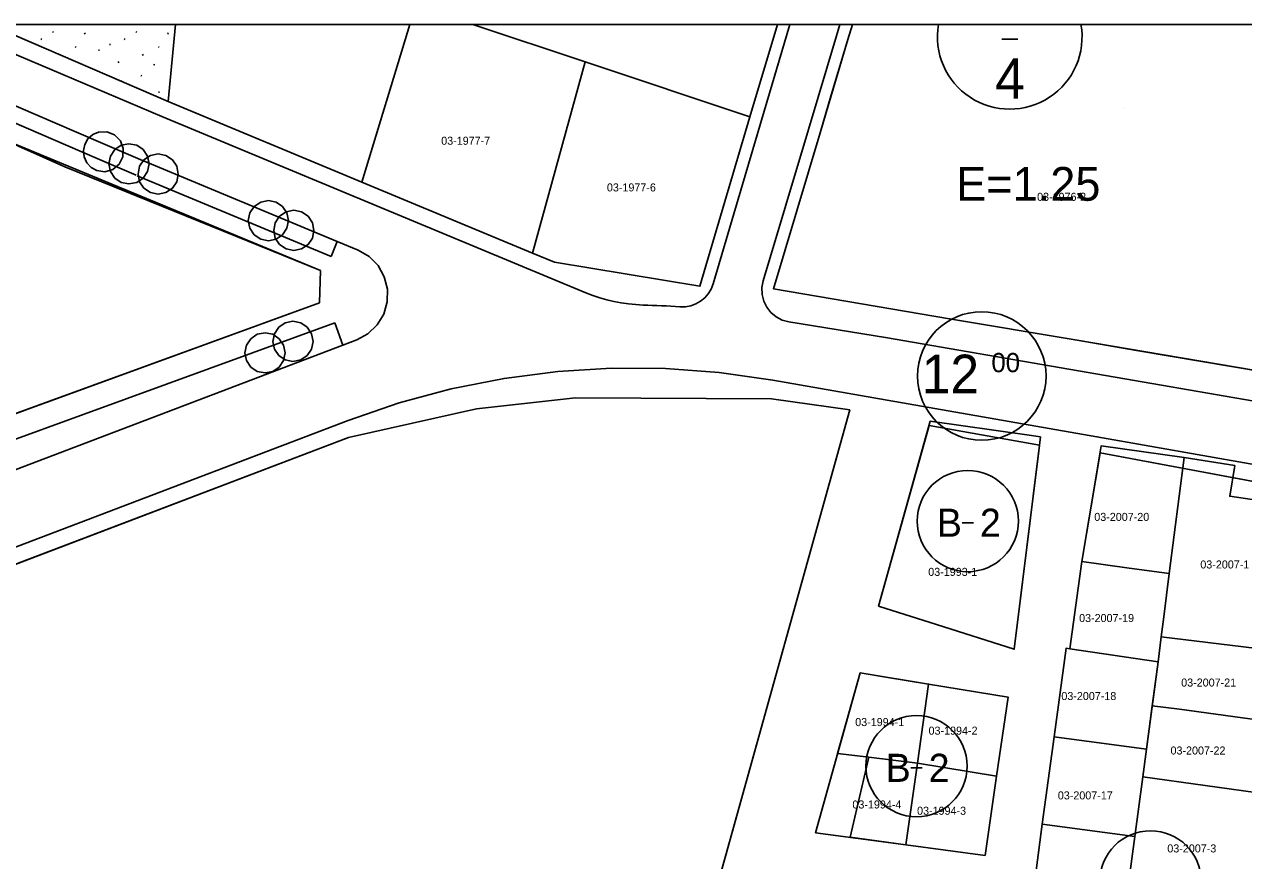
# Model space of a CAD drawing. Extents: x 413946 to 415528, y 4453939 to 4454944.
# Drawn here: x 414198.6 to 414350.4, y 4454839.9 to 4454944 of the extents above; entities that cross this region are included whole.
import ezdxf

# ---------------------------------------------------------------- set-up
doc = ezdxf.new("R2010")
doc.units = 0
for name, color, linetype in [('0_KADASTRO', 7, 'Continuous'), ('0_ÇERÇEVE', 7, 'Continuous'), ('Level 27', 7, 'Continuous'), ('Level 28', 7, 'Continuous'), ('Level 34', 7, 'Continuous'), ('Level 41', 7, 'Continuous'), ('Level 54', 7, 'Continuous'), ('Level 62', 7, 'Continuous'), ('SEMBOL', 7, 'Continuous'), ('SNR_FONKSIYON', 7, 'Continuous')]:
    doc.layers.add(name, color=color, linetype=linetype)

msp = doc.modelspace()

# ---------------------------------------------------------------- linework, layer by layer
at = {"layer": '0_KADASTRO'}
for points in [[(414246.61, 4454943.96), (414240.66, 4454924.31), (414216.52, 4454934.35), (414217.44, 4454943.96)], [(414217.44, 4454943.96), (414246.61, 4454943.96)], [(414254.45, 4454943.96), (414268.47, 4454939.28), (414261.9, 4454915.48), (414240.66, 4454924.31), (414246.61, 4454943.96)], [(414246.61, 4454943.96), (414254.45, 4454943.96)], [(414254.45, 4454943.96), (414292.38, 4454943.96)], [(414292.38, 4454943.96), (414288.97, 4454932.45), (414268.47, 4454939.28), (414254.45, 4454943.96)], [(414364.2, 4454943.96), (414356.8, 4454900.03), (414337.07, 4454903.37), (414329.44, 4454904.67), (414313.82, 4454907.32), (414291.88, 4454911.04), (414297.69, 4454930.45), (414299.05, 4454935), (414301.17, 4454942.09), (414301.73, 4454943.96)], [(414301.73, 4454943.96), (414364.2, 4454943.96)]]:
    msp.add_lwpolyline(points, dxfattribs=at)
for points in [[(414261.9, 4454915.48), (414268.47, 4454939.28), (414288.97, 4454932.45), (414282.73, 4454911.35), (414264.63, 4454914.35)], [(414112.98, 4454904.87), (414193.33, 4454930.76), (414235.49, 4454913.3), (414235.37, 4454909.28), (414125.89, 4454869.42)], [(414096.99, 4454835.77), (414098.7, 4454839.14), (414238.98, 4454892.53), (414254.93, 4454896.1), (414267.24, 4454897.45), (414291.64, 4454897.36), (414301.38, 4454895.97), (414237.57, 4454666.8), (414236.56, 4454663.13), (414213.19, 4454675.19), (414204.39, 4454687.27), (414188.47, 4454709.34), (414167.47, 4454738.38)], [(414304.98, 4454871.51), (414311.4, 4454894.55), (414315.23, 4454894), (414323.43, 4454892.84), (414325.13, 4454892.59), (414324.92, 4454890.87), (414321.86, 4454866.17), (414312.17, 4454869.24)], [(414330.3, 4454877.07), (414331.21, 4454882.53), (414332.7, 4454891.5), (414343, 4454890.03), (414341.16, 4454875.58), (414335.89, 4454876.3)], [(414340.17, 4454867.72), (414340.49, 4454870.19), (414341.16, 4454875.58), (414343, 4454890.03), (414349.31, 4454889.04), (414348.7, 4454885.22), (414358.7, 4454883.73), (414357.14, 4454871.64), (414356.23, 4454865.76)], [(414328.8, 4454866.22), (414330.3, 4454877.07), (414335.89, 4454876.3), (414341.16, 4454875.58), (414340.49, 4454870.19), (414340.17, 4454867.72), (414339.77, 4454864.6)], [(414339.04, 4454859.14), (414339.77, 4454864.6), (414340.17, 4454867.72), (414356.23, 4454865.76), (414354.79, 4454857.02), (414342.43, 4454858.69)], [(414326.83, 4454855.25), (414328.31, 4454866.29), (414328.8, 4454866.22), (414339.77, 4454864.6), (414338.32, 4454853.74)], [(414299.88, 4454853.18), (414302.67, 4454863.22), (414306.12, 4454862.65), (414311.21, 4454861.83), (414309.81, 4454851.98), (414303.77, 4454852.71)], [(414309.81, 4454851.98), (414311.21, 4454861.83), (414321.1, 4454860.2), (414319.67, 4454850.37)], [(414337.87, 4454850.29), (414338.32, 4454853.74), (414339.04, 4454859.14), (414342.43, 4454858.69), (414354.79, 4454857.02), (414353.41, 4454848.13)], [(414325.36, 4454844.37), (414326.83, 4454855.25), (414338.32, 4454853.74), (414337.87, 4454850.29), (414336.89, 4454842.85)], [(414301.42, 4454842.75), (414303.77, 4454852.71), (414309.81, 4454851.98), (414308.36, 4454841.83)], [(414308.36, 4454841.83), (414309.81, 4454851.98), (414319.67, 4454850.37), (414318.23, 4454840.49)], [(414335.69, 4454833.87), (414336.89, 4454842.85), (414337.87, 4454850.29), (414353.41, 4454848.13), (414351.45, 4454831.76)], [(414324.04, 4454834.47), (414325.36, 4454844.37), (414336.89, 4454842.85), (414335.69, 4454833.87), (414335.56, 4454832.91)]]:
    msp.add_lwpolyline(points, close=True, dxfattribs=at)
at = {"layer": '0_ÇERÇEVE'}
msp.add_lwpolyline([(413945.57, 4454943.96), (415494.14, 4454943.96), (415494.14, 4453939.48), (413945.57, 4453939.48)], close=True, dxfattribs=at)
at = {"layer": 'Level 27'}
for p, q in [((414311.26, 4454894.04), (414325.01, 4454891.56)), ((414325.01, 4454891.56), (414321.86, 4454866.17)), ((414330.3, 4454877.07), (414332.55, 4454890.62)), ((414332.55, 4454890.62), (414358.97, 4454885.69)), ((414328.8, 4454866.22), (414330.3, 4454877.07)), ((414312.17, 4454869.24), (414304.98, 4454871.51)), ((414321.86, 4454866.17), (414312.17, 4454869.24)), ((414326.83, 4454855.25), (414328.31, 4454866.29)), ((414328.31, 4454866.29), (414328.8, 4454866.22)), ((414302.67, 4454863.22), (414311.21, 4454861.83)), ((414311.21, 4454861.83), (414321.1, 4454860.2)), ((414321.1, 4454860.2), (414319.67, 4454850.37)), ((414325.36, 4454844.37), (414326.83, 4454855.25)), ((414319.67, 4454850.37), (414318.23, 4454840.49)), ((414324.04, 4454834.47), (414325.36, 4454844.37)), ((414308.36, 4454841.83), (414297.14, 4454843.32)), ((414318.23, 4454840.49), (414308.36, 4454841.83))]:
    msp.add_line(p, q, dxfattribs=at)
at = {"layer": 'Level 28'}
for p, q in [((414292.38, 4454943.96), (414288.97, 4454932.45)), ((414301.17, 4454942.09), (414301.73, 4454943.96)), ((414216.52, 4454934.35), (414195.55, 4454943.39)), ((414297.69, 4454930.45), (414301.17, 4454942.09)), ((414240.66, 4454924.31), (414216.52, 4454934.35)), ((414288.97, 4454932.45), (414282.73, 4454911.35)), ((414193.46, 4454930.78), (414203.67, 4454926.21)), ((414291.88, 4454911.04), (414297.69, 4454930.45)), ((414203.67, 4454926.21), (414235.49, 4454913.3)), ((414261.9, 4454915.48), (414240.66, 4454924.31)), ((414264.63, 4454914.35), (414261.9, 4454915.48)), ((414282.73, 4454911.35), (414264.63, 4454914.35)), ((414235.49, 4454913.3), (414235.37, 4454909.28)), ((414313.82, 4454907.32), (414291.88, 4454911.04)), ((414235.37, 4454909.28), (414024.52, 4454832.51)), ((414329.44, 4454904.67), (414313.82, 4454907.32)), ((414356.8, 4454900.03), (414329.44, 4454904.67)), ((414254.93, 4454896.1), (414267.24, 4454897.45)), ((414267.24, 4454897.45), (414291.64, 4454897.36)), ((414291.64, 4454897.36), (414301.38, 4454895.97)), ((414301.38, 4454895.97), (414237.57, 4454666.8)), ((414238.98, 4454892.53), (414254.93, 4454896.1)), ((414304.98, 4454871.51), (414311.26, 4454894.04)), ((414098.7, 4454839.14), (414238.98, 4454892.53)), ((414297.14, 4454843.32), (414302.67, 4454863.22))]:
    msp.add_line(p, q, dxfattribs=at)
at = {"layer": 'Level 34'}
for points in [[(414364.2, 4454943.96), (414356.8, 4454900.03), (414329.44, 4454904.67), (414313.82, 4454907.32), (414291.88, 4454911.04), (414297.69, 4454930.45), (414301.17, 4454942.09), (414301.73, 4454943.96)], [(414301.73, 4454943.96), (414364.2, 4454943.96)]]:
    msp.add_lwpolyline(points, dxfattribs=at)
at = {"layer": 'Level 41'}
for p, q in [((414202.15, 4454943.01), (414202.28, 4454942.99)), ((414202.15, 4454943.01), (414202.28, 4454942.99)), ((414206.19, 4454942.73), (414206.12, 4454942.89)), ((414206.19, 4454942.73), (414206.12, 4454942.89)), ((414212.52, 4454943.01), (414212.65, 4454942.99)), ((414212.52, 4454943.01), (414212.65, 4454942.99)), ((414216.56, 4454942.73), (414216.49, 4454942.89)), ((414216.56, 4454942.73), (414216.49, 4454942.89)), ((414200.68, 4454942.17), (414200.81, 4454942.07)), ((414200.68, 4454942.17), (414200.81, 4454942.07)), ((414204.95, 4454941.16), (414205.07, 4454941.14)), ((414204.95, 4454941.16), (414205.07, 4454941.14)), ((414209.25, 4454941.47), (414209.38, 4454941.44)), ((414209.25, 4454941.47), (414209.38, 4454941.44)), ((414211.05, 4454942.17), (414211.17, 4454942.07)), ((414211.05, 4454942.17), (414211.17, 4454942.07)), ((414215.32, 4454941.16), (414215.44, 4454941.14)), ((414215.32, 4454941.16), (414215.44, 4454941.14)), ((414203.01, 4454940.17), (414202.98, 4454940.26)), ((414203.01, 4454940.17), (414202.98, 4454940.26)), ((414207.88, 4454940.75), (414208, 4454940.73)), ((414207.88, 4454940.75), (414208, 4454940.73)), ((414213.41, 4454940.09), (414213.35, 4454940.26)), ((414213.41, 4454940.09), (414213.35, 4454940.26)), ((414210.38, 4454939.18), (414210.32, 4454939.34)), ((414210.38, 4454939.18), (414210.32, 4454939.34)), ((414214.73, 4454938.96), (414214.86, 4454938.93)), ((414214.73, 4454938.96), (414214.86, 4454938.93)), ((414210.75, 4454936.84), (414210.7, 4454936.96)), ((414210.75, 4454936.84), (414210.7, 4454936.96)), ((414213.13, 4454937.59), (414213.25, 4454937.57)), ((414213.13, 4454937.59), (414213.25, 4454937.57)), ((414215.34, 4454935.52), (414215.47, 4454935.5)), ((414215.34, 4454935.52), (414215.47, 4454935.5))]:
    msp.add_line(p, q, dxfattribs=at)
at = {"layer": 'Level 54'}
msp.add_line((414335.48, 4454933.67), (414335.48, 4454933.67), dxfattribs=at)
for points in [[(414292.38, 4454943.96), (414288.97, 4454932.45), (414282.73, 4454911.35), (414264.63, 4454914.35), (414261.9, 4454915.48), (414240.66, 4454924.31), (414216.52, 4454934.35), (414217.44, 4454943.96)], [(414217.44, 4454943.96), (414292.38, 4454943.96)], [(414324.04, 4454834.47), (414325.36, 4454844.37), (414326.83, 4454855.25), (414328.31, 4454866.29), (414328.8, 4454866.22), (414330.3, 4454877.07), (414332.55, 4454890.62), (414358.97, 4454885.69)]]:
    msp.add_lwpolyline(points, dxfattribs=at)
for points in [[(414235.37, 4454909.28), (414024.52, 4454832.51), (414037.38, 4454880.41), (414193.46, 4454930.78), (414203.67, 4454926.21), (414235.49, 4454913.3)], [(414098.7, 4454839.14), (414238.98, 4454892.53), (414254.93, 4454896.1), (414267.24, 4454897.45), (414291.64, 4454897.36), (414301.38, 4454895.97), (414237.57, 4454666.8), (414236.56, 4454663.13), (414213.19, 4454675.19), (414204.39, 4454687.27), (414188.47, 4454709.34), (414167.47, 4454738.38), (414096.99, 4454835.77), (414098.7, 4454839.14)], [(414325.01, 4454891.56), (414321.86, 4454866.17), (414312.17, 4454869.24), (414304.98, 4454871.51), (414311.26, 4454894.04)], [(414319.67, 4454850.37), (414318.23, 4454840.49), (414308.36, 4454841.83), (414297.14, 4454843.32), (414302.67, 4454863.22), (414311.21, 4454861.83), (414321.1, 4454860.2)]]:
    msp.add_lwpolyline(points, close=True, dxfattribs=at)
at = {"layer": 'Level 62'}
for p, q in [((414215.75, 4454932.5), (414188.62, 4454943.96)), ((414207.82, 4454929.39), (414192.38, 4454936.04)), ((414207.71, 4454927.26), (414194.91, 4454932.78)), ((414268.54, 4454910.55), (414215.75, 4454932.5)), ((414213.35, 4454927), (414207.82, 4454929.39)), ((414209.89, 4454928.37), (414210.7, 4454928.91)), ((414210.7, 4454928.91), (414211.66, 4454929.1)), ((414211.66, 4454929.1), (414212.62, 4454928.91)), ((414212.62, 4454928.91), (414213.43, 4454928.37)), ((414212.56, 4454925.17), (414207.71, 4454927.26)), ((414209.16, 4454926.6), (414209.35, 4454927.55)), ((414209.35, 4454927.55), (414209.89, 4454928.37)), ((414213.43, 4454928.37), (414213.97, 4454927.55)), ((414213.53, 4454927.1), (414214.34, 4454927.64)), ((414213.97, 4454927.55), (414214.16, 4454926.6)), ((414214.34, 4454927.64), (414215.3, 4454927.83)), ((414215.3, 4454927.83), (414216.26, 4454927.64)), ((414216.26, 4454927.64), (414217.07, 4454927.1)), ((414209.35, 4454925.64), (414209.16, 4454926.6)), ((414212.8, 4454925.33), (414212.99, 4454926.29)), ((414212.99, 4454926.29), (414213.53, 4454927.1)), ((414237.59, 4454916.92), (414213.45, 4454926.96)), ((414214.16, 4454926.6), (414213.97, 4454925.64)), ((414217.07, 4454927.1), (414217.61, 4454926.29)), ((414217.61, 4454926.29), (414217.8, 4454925.33)), ((414209.89, 4454924.83), (414209.35, 4454925.64)), ((414210.7, 4454924.29), (414209.89, 4454924.83)), ((414211.66, 4454924.1), (414210.7, 4454924.29)), ((414212.62, 4454924.29), (414211.66, 4454924.1)), ((414213.43, 4454924.83), (414212.62, 4454924.29)), ((414236.82, 4454915.08), (414212.68, 4454925.12)), ((414212.99, 4454924.37), (414212.8, 4454925.33)), ((414213.53, 4454923.56), (414212.99, 4454924.37)), ((414213.97, 4454925.64), (414213.43, 4454924.83)), ((414217.61, 4454924.37), (414217.07, 4454923.56)), ((414217.8, 4454925.33), (414217.61, 4454924.37)), ((414214.34, 4454923.02), (414213.53, 4454923.56)), ((414215.3, 4454922.83), (414214.34, 4454923.02)), ((414216.26, 4454923.02), (414215.3, 4454922.83)), ((414217.07, 4454923.56), (414216.26, 4454923.02)), ((414226.71, 4454920.48), (414227.25, 4454921.29)), ((414227.25, 4454921.29), (414228.06, 4454921.84)), ((414228.06, 4454921.84), (414229.02, 4454922.03)), ((414229.02, 4454922.03), (414229.98, 4454921.84)), ((414229.98, 4454921.84), (414230.79, 4454921.29)), ((414230.79, 4454921.29), (414231.33, 4454920.48)), ((414226.52, 4454919.53), (414226.71, 4454920.48)), ((414229.88, 4454919.27), (414230.42, 4454920.08)), ((414230.42, 4454920.08), (414231.23, 4454920.62)), ((414231.23, 4454920.62), (414232.19, 4454920.81)), ((414231.33, 4454920.48), (414231.52, 4454919.53)), ((414232.19, 4454920.81), (414233.14, 4454920.62)), ((414233.14, 4454920.62), (414233.95, 4454920.08)), ((414233.95, 4454920.08), (414234.5, 4454919.27)), ((414226.71, 4454918.57), (414226.52, 4454919.53)), ((414227.25, 4454917.76), (414226.71, 4454918.57)), ((414229.69, 4454918.31), (414229.88, 4454919.27)), ((414229.88, 4454917.36), (414229.69, 4454918.31)), ((414231.33, 4454918.57), (414230.79, 4454917.76)), ((414231.52, 4454919.53), (414231.33, 4454918.57)), ((414234.5, 4454919.27), (414234.69, 4454918.31)), ((414234.69, 4454918.31), (414234.5, 4454917.36)), ((414228.06, 4454917.22), (414227.25, 4454917.76)), ((414229.02, 4454917.03), (414228.06, 4454917.22)), ((414229.98, 4454917.22), (414229.02, 4454917.03)), ((414230.42, 4454916.55), (414229.88, 4454917.36)), ((414230.79, 4454917.76), (414229.98, 4454917.22)), ((414234.5, 4454917.36), (414233.95, 4454916.55)), ((414236.82, 4454915.08), (414237.59, 4454916.92)), ((414240.19, 4454915.84), (414237.59, 4454916.92)), ((414231.23, 4454916), (414230.42, 4454916.55)), ((414232.19, 4454915.81), (414231.23, 4454916)), ((414233.14, 4454916), (414232.19, 4454915.81)), ((414233.95, 4454916.55), (414233.14, 4454916)), ((414229.77, 4454905.44), (414230.31, 4454906.26)), ((414230.31, 4454906.26), (414231.12, 4454906.8)), ((414231.12, 4454906.8), (414232.08, 4454906.99)), ((414232.08, 4454906.99), (414233.04, 4454906.8)), ((414233.04, 4454906.8), (414233.85, 4454906.26)), ((414233.85, 4454906.26), (414234.39, 4454905.44)), ((414237.28, 4454906.79), (414238.28, 4454904.03)), ((414305.85, 4454904.98), (414293.8, 4454906.92)), ((414226.29, 4454904.02), (414226.83, 4454904.83)), ((414226.83, 4454904.83), (414227.64, 4454905.37)), ((414227.64, 4454905.37), (414228.6, 4454905.56)), ((414228.6, 4454905.56), (414229.56, 4454905.37)), ((414229.56, 4454905.37), (414230.37, 4454904.83)), ((414229.58, 4454904.49), (414229.77, 4454905.44)), ((414229.77, 4454903.53), (414229.58, 4454904.49)), ((414230.37, 4454904.83), (414230.91, 4454904.02)), ((414234.39, 4454905.44), (414234.58, 4454904.49)), ((414234.58, 4454904.49), (414234.39, 4454903.53)), ((414305.85, 4454904.98), (414409.67, 4454887.05)), ((414226.1, 4454903.06), (414226.29, 4454904.02)), ((414226.29, 4454902.11), (414226.1, 4454903.06)), ((414230.31, 4454902.72), (414229.77, 4454903.53)), ((414230.91, 4454904.02), (414231.1, 4454903.06)), ((414231.1, 4454903.06), (414230.91, 4454902.11)), ((414234.39, 4454903.53), (414233.85, 4454902.72)), ((414226.83, 4454901.29), (414226.29, 4454902.11)), ((414231.12, 4454902.18), (414230.31, 4454902.72)), ((414230.91, 4454902.11), (414230.37, 4454901.29)), ((414232.08, 4454901.99), (414231.12, 4454902.18)), ((414233.04, 4454902.18), (414232.08, 4454901.99)), ((414233.85, 4454902.72), (414233.04, 4454902.18)), ((414227.64, 4454900.75), (414226.83, 4454901.29)), ((414228.6, 4454900.56), (414227.64, 4454900.75)), ((414229.56, 4454900.75), (414228.6, 4454900.56)), ((414230.37, 4454901.29), (414229.56, 4454900.75))]:
    msp.add_line(p, q, dxfattribs=at)
for points in [[(414293.94, 4454943.96), (414290.41, 4454932.02), (414284.38, 4454911.64)], [(414290.61, 4454912.02), (414296.25, 4454930.88), (414299.73, 4454942.52), (414300.16, 4454943.96)], [(414207.88, 4454930.54), (414207.15, 4454930.23), (414206.55, 4454929.71), (414206.15, 4454929.02), (414205.99, 4454928.24), (414206.07, 4454927.45), (414206.4, 4454926.73), (414206.94, 4454926.15), (414207.64, 4454925.76)], [(414207.64, 4454925.76), (414208.65, 4454925.62), (414209.64, 4454925.9), (414210.44, 4454926.56), (414210.9, 4454927.48), (414210.95, 4454928.5), (414210.59, 4454929.46), (414209.87, 4454930.2), (414208.91, 4454930.58), (414207.88, 4454930.54)], [(414240.02, 4454904.69), (414241.41, 4454905.45), (414242.56, 4454906.54), (414243.38, 4454907.9), (414243.82, 4454909.42), (414243.84, 4454911), (414243.45, 4454912.54), (414242.67, 4454913.92), (414241.56, 4454915.05), (414240.19, 4454915.84)], [(414268.54, 4454910.55), (414269.4, 4454910.22), (414270.26, 4454909.92), (414271.14, 4454909.67), (414272.03, 4454909.46), (414272.93, 4454909.29), (414273.84, 4454909.16), (414274.75, 4454909.07), (414275.66, 4454909.02)], [(414280.25, 4454908.79), (414280.93, 4454908.8), (414281.59, 4454908.92), (414282.23, 4454909.15), (414282.82, 4454909.49), (414283.34, 4454909.92), (414283.78, 4454910.43), (414284.13, 4454911.01), (414284.38, 4454911.64)], [(414290.61, 4454912.02), (414290.45, 4454911.18), (414290.48, 4454910.33), (414290.68, 4454909.51), (414291.05, 4454908.75), (414291.58, 4454908.08), (414292.23, 4454907.54), (414292.98, 4454907.14), (414293.8, 4454906.92)], [(414280.25, 4454908.79), (414279.68, 4454908.83), (414279.1, 4454908.87), (414278.53, 4454908.9), (414277.96, 4454908.93), (414277.38, 4454908.96), (414276.81, 4454908.98), (414276.24, 4454909.01), (414275.66, 4454909.02)], [(414237.28, 4454906.79), (414206.07, 4454895.42)], [(414096.8, 4454850.19), (414131.17, 4454863.27), (414135.84, 4454865.05), (414238.28, 4454904.03), (414240.02, 4454904.69)], [(414291.8, 4454899.68), (414285.15, 4454900.62), (414278.45, 4454901.11), (414271.73, 4454901.15), (414265.03, 4454900.74), (414258.36, 4454899.88), (414251.77, 4454898.57), (414245.29, 4454896.83), (414238.93, 4454894.65)], [(414291.8, 4454899.68), (414332.16, 4454892.61), (414358.52, 4454887.95)], [(414206.07, 4454895.42), (414134.3, 4454869.29)], [(414205.37, 4454881.88), (414238.93, 4454894.65)], [(414100.09, 4454841.81), (414205.37, 4454881.88)]]:
    msp.add_lwpolyline(points, dxfattribs=at)
at = {"layer": 'SEMBOL'}
for p, q in [((414320.31, 4454942.1), (414322.31, 4454942.1)), ((414315.38, 4454881.91), (414316.78, 4454881.91)), ((414309, 4454851.4), (414310.4, 4454851.4))]:
    msp.add_line(p, q, dxfattribs=at)
msp.add_lwpolyline([(414330.17, 4454943.96), (414312.44, 4454943.96)], dxfattribs=at)
for centre, radius in [((414317.82, 4454900.18), 8), ((414316.08, 4454882.12), 6.3), ((414309.7, 4454851.61), 6.3), ((414338.83, 4454837.27), 6.3)]:
    msp.add_circle(centre, radius, dxfattribs=at)
msp.add_arc((414321.31, 4454942.4), 9, 170.0172, 9.9828, dxfattribs=at)
at = {"layer": 'SNR_FONKSIYON'}
msp.add_line((414217.44, 4454943.96), (414216.52, 4454934.35), dxfattribs=at)

# ---------------------------------------------------------------- texts
at = {"layer": '0_KADASTRO'}
for s, p in [('03-1977-7', (414250.53, 4454928.97)), ('03-1977-6', (414271.16, 4454923.16)), ('03-1976-2', (414324.71, 4454921.99)), ('03-2007-20', (414331.83, 4454882.14)), ('03-2007-1', (414345.03, 4454876.22)), ('03-1993-1', (414311.16, 4454875.3)), ('03-2007-19', (414329.94, 4454869.55)), ('03-2007-21', (414342.65, 4454861.52)), ('03-2007-18', (414327.73, 4454859.84)), ('03-1994-1', (414302.07, 4454856.6)), ('03-1994-2', (414311.2, 4454855.53)), ('03-2007-22', (414341.32, 4454853.06)), ('03-2007-17', (414327.29, 4454847.47)), ('03-1994-4', (414301.72, 4454846.34)), ('03-1994-3', (414309.77, 4454845.56)), ('03-2007-3', (414340.92, 4454840.87))]:
    msp.add_text(s, height=1, dxfattribs=at).set_placement(p)
at = {"layer": 'SEMBOL'}
for s, height, p in [('4', 5, (414319.47, 4454934.72)), ('E=1.25', 4.2, (414314.64, 4454922)), ('00', 2.4, (414319.02, 4454900.65)), ('12', 4.8, (414310.35, 4454898.04)), ('B', 3.5, (414312.23, 4454880.16)), ('2', 3.5, (414317.59, 4454880.16)), ('B', 3.5, (414305.86, 4454849.65)), ('2', 3.5, (414311.21, 4454849.65))]:
    msp.add_text(s, height=height, dxfattribs=at).set_placement(p)

doc.saveas('drawing.dxf')
